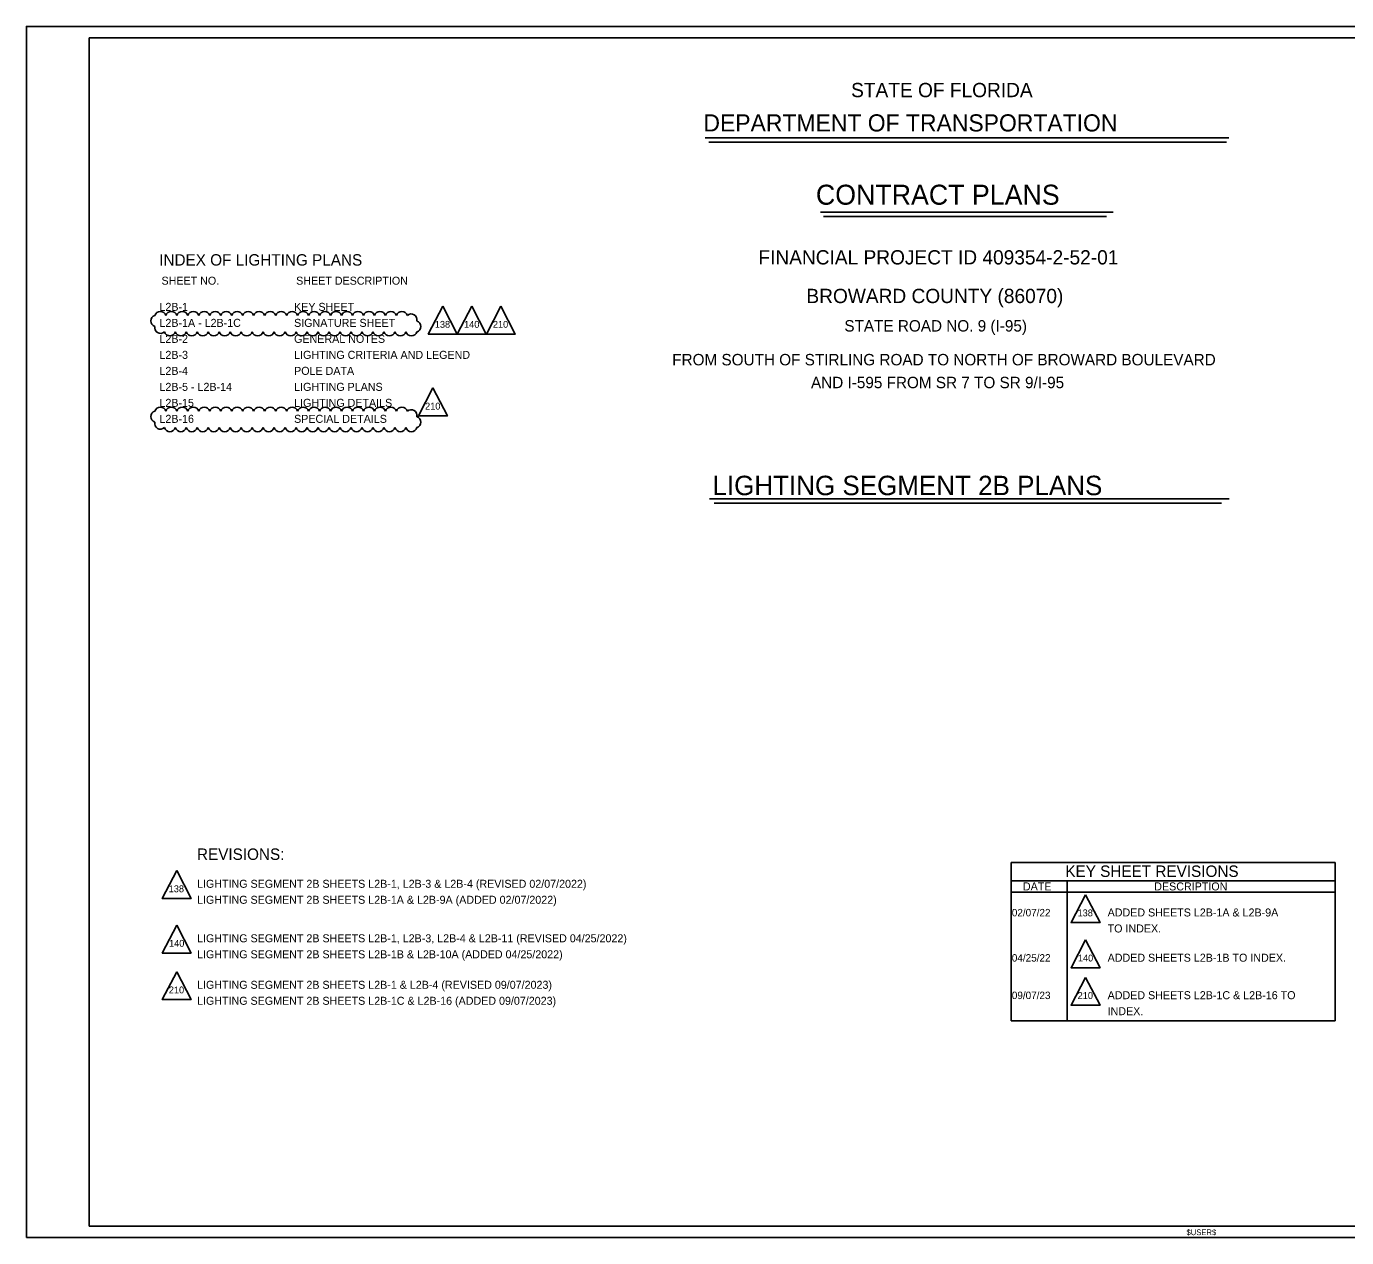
# Model space of a CAD drawing. Extents: x -820.2 to -798.1, y -2199.1 to -2188.5.
# Drawn here: x -820.23 to -808.68, y -2199.12 to -2188.52 of the extents above; entities that cross this region are included whole.
import ezdxf

# ---------------------------------------------------------------- set-up
doc = ezdxf.new("R2010")
doc.units = 0
for name, color, linetype in [('AdhocPoint_dp', 7, 'Continuous'), ('Cloud_dp', 7, 'Continuous'), ('PlotBorder_dp', 7, 'Continuous'), ('SheetBorder_dp', 7, 'Continuous'), ('SumBoxLines_dp', 7, 'Continuous'), ('TextLabel', 7, 'Continuous'), ('TextMinor', 7, 'Continuous'), ('TextNotes', 7, 'Continuous'), ('TextTitle', 7, 'Continuous')]:
    doc.layers.add(name, color=color, linetype=linetype)

msp = doc.modelspace()

# ---------------------------------------------------------------- linework, layer by layer
at = {"layer": 'AdhocPoint_dp'}
msp.add_line((-820.227, -2199.124), (-820.227, -2199.124), dxfattribs=at)
at = {"layer": 'Cloud_dp'}
for points in [[(-816.585, -2190.972), (-816.711, -2191.216), (-816.458, -2191.216)], [(-816.331, -2190.972), (-816.458, -2191.216), (-816.204, -2191.216)], [(-816.077, -2190.972), (-816.203, -2191.216), (-815.95, -2191.216)], [(-816.67, -2191.688), (-816.797, -2191.932), (-816.544, -2191.932)], [(-818.912, -2195.912), (-819.039, -2196.156), (-818.786, -2196.156)], [(-810.961, -2196.123), (-811.088, -2196.367), (-810.834, -2196.367)], [(-818.912, -2196.389), (-819.039, -2196.633), (-818.786, -2196.633)], [(-810.961, -2196.518), (-811.088, -2196.762), (-810.834, -2196.762)], [(-818.912, -2196.797), (-819.039, -2197.041), (-818.786, -2197.041)], [(-810.961, -2196.846), (-811.088, -2197.09), (-810.834, -2197.09)]]:
    msp.add_lwpolyline(points, close=True, dxfattribs=at)
for centre, radius, start, end in [((-819.088, -2191.101), 0.0504, 107.5, 252.5), ((-819.055, -2191.068), 0.0504, 17.5, 162.5), ((-818.959, -2191.068), 0.0504, 17.5, 162.5), ((-818.863, -2191.068), 0.0504, 17.5, 162.5), ((-818.767, -2191.068), 0.0504, 17.5, 162.5), ((-818.671, -2191.068), 0.0504, 17.5, 162.5), ((-818.575, -2191.068), 0.0504, 17.5, 162.5), ((-818.479, -2191.068), 0.0504, 17.5, 162.5), ((-818.383, -2191.068), 0.0504, 17.5, 162.5), ((-818.287, -2191.068), 0.0504, 17.5, 162.5), ((-818.191, -2191.068), 0.0504, 17.5, 162.5), ((-818.094, -2191.068), 0.0504, 17.5, 162.5), ((-817.998, -2191.068), 0.0504, 17.5, 162.5), ((-817.902, -2191.068), 0.0504, 17.5, 162.5), ((-817.806, -2191.068), 0.0504, 17.5, 162.5), ((-817.71, -2191.068), 0.0504, 17.5, 162.5), ((-817.614, -2191.068), 0.0504, 17.5, 162.5), ((-817.518, -2191.068), 0.0504, 17.5, 162.5), ((-817.422, -2191.068), 0.0504, 17.5, 162.5), ((-817.326, -2191.068), 0.0504, 17.5, 162.5), ((-817.23, -2191.068), 0.0504, 17.5, 162.5), ((-817.134, -2191.068), 0.0504, 17.5, 162.5), ((-817.038, -2191.068), 0.0504, 17.5, 162.5), ((-816.942, -2191.068), 0.0504, 17.5, 162.5), ((-816.86, -2191.09), 0.0503, 347.2695, 132.2695), ((-819.054, -2191.16), 0.0503, 167.2695, 312.2695), ((-816.826, -2191.15), 0.0504, 287.5, 72.5), ((-818.972, -2191.182), 0.0504, 197.5, 342.5), ((-818.876, -2191.182), 0.0504, 197.5, 342.5), ((-818.78, -2191.182), 0.0504, 197.5, 342.5), ((-818.684, -2191.182), 0.0504, 197.5, 342.5), ((-818.588, -2191.182), 0.0504, 197.5, 342.5), ((-818.492, -2191.182), 0.0504, 197.5, 342.5), ((-818.396, -2191.182), 0.0504, 197.5, 342.5), ((-818.3, -2191.182), 0.0504, 197.5, 342.5), ((-818.204, -2191.182), 0.0504, 197.5, 342.5), ((-818.108, -2191.182), 0.0504, 197.5, 342.5), ((-818.012, -2191.182), 0.0504, 197.5, 342.5), ((-817.915, -2191.182), 0.0504, 197.5, 342.5), ((-817.819, -2191.182), 0.0504, 197.5, 342.5), ((-817.723, -2191.182), 0.0504, 197.5, 342.5), ((-817.627, -2191.182), 0.0504, 197.5, 342.5), ((-817.531, -2191.182), 0.0504, 197.5, 342.5), ((-817.435, -2191.182), 0.0504, 197.5, 342.5), ((-817.339, -2191.182), 0.0504, 197.5, 342.5), ((-817.243, -2191.182), 0.0504, 197.5, 342.5), ((-817.147, -2191.182), 0.0504, 197.5, 342.5), ((-817.051, -2191.182), 0.0504, 197.5, 342.5), ((-816.955, -2191.182), 0.0504, 197.5, 342.5), ((-816.859, -2191.182), 0.0504, 197.5, 342.5), ((-819.055, -2191.906), 0.0504, 17.5, 162.5), ((-818.959, -2191.906), 0.0504, 17.5, 162.5), ((-818.863, -2191.906), 0.0504, 17.5, 162.5), ((-818.767, -2191.906), 0.0504, 17.5, 162.5), ((-818.671, -2191.906), 0.0504, 17.5, 162.5), ((-818.575, -2191.906), 0.0504, 17.5, 162.5), ((-818.479, -2191.906), 0.0504, 17.5, 162.5), ((-818.383, -2191.906), 0.0504, 17.5, 162.5), ((-818.287, -2191.906), 0.0504, 17.5, 162.5), ((-818.191, -2191.906), 0.0504, 17.5, 162.5), ((-818.094, -2191.906), 0.0504, 17.5, 162.5), ((-817.998, -2191.906), 0.0504, 17.5, 162.5), ((-817.902, -2191.906), 0.0504, 17.5, 162.5), ((-817.806, -2191.906), 0.0504, 17.5, 162.5), ((-817.71, -2191.906), 0.0504, 17.5, 162.5), ((-817.614, -2191.906), 0.0504, 17.5, 162.5), ((-817.518, -2191.906), 0.0504, 17.5, 162.5), ((-817.422, -2191.906), 0.0504, 17.5, 162.5), ((-817.326, -2191.906), 0.0504, 17.5, 162.5), ((-817.23, -2191.906), 0.0504, 17.5, 162.5), ((-817.134, -2191.906), 0.0504, 17.5, 162.5), ((-817.038, -2191.906), 0.0504, 17.5, 162.5), ((-816.942, -2191.906), 0.0504, 17.5, 162.5), ((-816.86, -2191.928), 0.0503, 347.2695, 132.2695), ((-819.088, -2191.938), 0.0504, 107.5, 252.5), ((-819.054, -2191.998), 0.0503, 167.2695, 312.2695), ((-816.826, -2191.987), 0.0504, 287.5, 72.5), ((-818.972, -2192.02), 0.0504, 197.5, 342.5), ((-818.876, -2192.02), 0.0504, 197.5, 342.5), ((-818.78, -2192.02), 0.0504, 197.5, 342.5), ((-818.684, -2192.02), 0.0504, 197.5, 342.5), ((-818.588, -2192.02), 0.0504, 197.5, 342.5), ((-818.492, -2192.02), 0.0504, 197.5, 342.5), ((-818.396, -2192.02), 0.0504, 197.5, 342.5), ((-818.3, -2192.02), 0.0504, 197.5, 342.5), ((-818.204, -2192.02), 0.0504, 197.5, 342.5), ((-818.108, -2192.02), 0.0504, 197.5, 342.5), ((-818.012, -2192.02), 0.0504, 197.5, 342.5), ((-817.915, -2192.02), 0.0504, 197.5, 342.5), ((-817.819, -2192.02), 0.0504, 197.5, 342.5), ((-817.723, -2192.02), 0.0504, 197.5, 342.5), ((-817.627, -2192.02), 0.0504, 197.5, 342.5), ((-817.531, -2192.02), 0.0504, 197.5, 342.5), ((-817.435, -2192.02), 0.0504, 197.5, 342.5), ((-817.339, -2192.02), 0.0504, 197.5, 342.5), ((-817.243, -2192.02), 0.0504, 197.5, 342.5), ((-817.147, -2192.02), 0.0504, 197.5, 342.5), ((-817.051, -2192.02), 0.0504, 197.5, 342.5), ((-816.955, -2192.02), 0.0504, 197.5, 342.5), ((-816.859, -2192.02), 0.0504, 197.5, 342.5)]:
    msp.add_arc(centre, radius, start, end, dxfattribs=at)
at = {"layer": 'PlotBorder_dp'}
msp.add_lwpolyline([(-820.227, -2199.124), (-803.727, -2199.124), (-803.727, -2188.524), (-820.227, -2188.524)], close=True, dxfattribs=at)
at = {"layer": 'SheetBorder_dp'}
for p, q in [((-819.677, -2188.624), (-819.677, -2199.024)), ((-819.677, -2188.624), (-804.277, -2188.624)), ((-819.677, -2199.024), (-804.277, -2199.024))]:
    msp.add_line(p, q, dxfattribs=at)
at = {"layer": 'SumBoxLines_dp'}
for p, q in [((-811.612, -2195.84), (-811.612, -2197.227)), ((-811.612, -2195.84), (-808.777, -2195.84)), ((-808.777, -2195.84), (-808.777, -2197.227)), ((-811.612, -2196), (-808.777, -2196)), ((-811.122, -2196), (-811.122, -2197.227)), ((-811.612, -2196.1), (-808.777, -2196.1)), ((-811.612, -2197.227), (-808.777, -2197.227))]:
    msp.add_line(p, q, dxfattribs=at)
at = {"layer": 'TextTitle'}
for p, q in [((-814.289, -2189.5), (-809.707, -2189.5)), ((-814.257, -2189.538), (-809.729, -2189.538)), ((-813.281, -2190.15), (-810.719, -2190.15)), ((-813.253, -2190.188), (-810.777, -2190.188)), ((-814.252, -2192.659), (-809.704, -2192.659)), ((-814.209, -2192.697), (-809.772, -2192.697))]:
    msp.add_line(p, q, dxfattribs=at)

# ---------------------------------------------------------------- texts
at = {"layer": 'Cloud_dp'}
for s, p in [('138', (-816.654, -2191.161)), ('140', (-816.398, -2191.161)), ('210', (-816.146, -2191.161)), ('210', (-816.739, -2191.877)), ('138', (-818.982, -2196.101)), ('138', (-811.031, -2196.312)), ('140', (-818.979, -2196.578)), ('140', (-811.028, -2196.707)), ('210', (-818.981, -2196.986)), ('210', (-811.03, -2197.035))]:
    msp.add_text(s, height=0.06, rotation=0, dxfattribs=at).set_placement(p)
at = {"layer": 'TextLabel'}
for s, height, p in [('FINANCIAL PROJECT ID 409354-2-52-01', 0.125, (-813.823, -2190.607)), ('INDEX OF LIGHTING PLANS', 0.1, (-819.065, -2190.617)), ('BROWARD COUNTY (86070)', 0.125, (-813.403, -2190.945)), ('L2B-1', 0.07, (-819.063, -2191.013)), ('KEY SHEET', 0.07, (-817.885, -2191.013)), ('L2B-1A - L2B-1C', 0.07, (-819.063, -2191.153)), ('SIGNATURE SHEET', 0.07, (-817.885, -2191.153)), ('STATE ROAD NO. 9 (I-95)', 0.1, (-813.071, -2191.194)), ('L2B-2', 0.07, (-819.063, -2191.293)), ('GENERAL NOTES', 0.07, (-817.885, -2191.293)), ('L2B-3', 0.07, (-819.063, -2191.433)), ('LIGHTING CRITERIA AND LEGEND', 0.07, (-817.885, -2191.433)), ('FROM SOUTH OF STIRLING ROAD TO NORTH OF BROWARD BOULEVARD', 0.1, (-814.577, -2191.49)), ('L2B-4', 0.07, (-819.063, -2191.573)), ('POLE DATA', 0.07, (-817.885, -2191.573)), ('L2B-5 - L2B-14', 0.07, (-819.063, -2191.713)), ('LIGHTING PLANS', 0.07, (-817.885, -2191.713)), ('AND I-595 FROM SR 7 TO SR 9/I-95', 0.1, (-813.363, -2191.69)), ('L2B-15', 0.07, (-819.063, -2191.853)), ('LIGHTING DETAILS', 0.07, (-817.885, -2191.853)), ('L2B-16', 0.07, (-819.063, -2191.993)), ('SPECIAL DETAILS', 0.07, (-817.885, -2191.993)), ('REVISIONS:', 0.1, (-818.735, -2195.818)), ('KEY SHEET REVISIONS', 0.1, (-811.138, -2195.967))]:
    msp.add_text(s, height=height, dxfattribs=at).set_placement(p)
at = {"layer": 'TextMinor'}
for s, height, p in [('02/07/22', 0.065, (-811.606, -2196.312)), ('ADDED SHEETS L2B-1A & L2B-9A ', 0.07, (-810.768, -2196.313)), ('TO INDEX.', 0.07, (-810.768, -2196.453)), ('04/25/22', 0.065, (-811.606, -2196.708)), ('ADDED SHEETS L2B-1B TO INDEX.', 0.07, (-810.768, -2196.709)), ('09/07/23', 0.065, (-811.606, -2197.036)), ('ADDED SHEETS L2B-1C & L2B-16 TO ', 0.07, (-810.768, -2197.037)), ('INDEX.', 0.07, (-810.768, -2197.177)), ('$USER$', 0.05, (-810.078, -2199.102))]:
    msp.add_text(s, height=height, dxfattribs=at).set_placement(p)
at = {"layer": 'TextNotes'}
for s, height, p in [('SHEET NO.', 0.07, (-819.045, -2190.784)), ('SHEET DESCRIPTION', 0.07, (-817.867, -2190.784)), ('LIGHTING SEGMENT 2B SHEETS L2B-1, L2B-3 & L2B-4 (REVISED 02/07/2022)', 0.06998, (-818.734, -2196.062)), ('DATE', 0.07, (-811.509, -2196.085)), ('DESCRIPTION', 0.07, (-810.36, -2196.085)), ('LIGHTING SEGMENT 2B SHEETS L2B-1A & L2B-9A (ADDED 02/07/2022)', 0.06998, (-818.734, -2196.202)), ('LIGHTING SEGMENT 2B SHEETS L2B-1, L2B-3, L2B-4 & L2B-11 (REVISED 04/25/2022)', 0.06998, (-818.734, -2196.539)), ('LIGHTING SEGMENT 2B SHEETS L2B-1B & L2B-10A (ADDED 04/25/2022)', 0.06998, (-818.734, -2196.679)), ('LIGHTING SEGMENT 2B SHEETS L2B-1 & L2B-4 (REVISED 09/07/2023)', 0.06998, (-818.734, -2196.946)), ('LIGHTING SEGMENT 2B SHEETS L2B-1C & L2B-16 (ADDED 09/07/2023)', 0.06998, (-818.734, -2197.086))]:
    msp.add_text(s, height=height, dxfattribs=at).set_placement(p)
at = {"layer": 'TextTitle'}
for s, height, p in [('STATE OF FLORIDA', 0.125, (-813.012, -2189.143)), ('DEPARTMENT OF TRANSPORTATION', 0.15, (-814.304, -2189.443)), ('CONTRACT PLANS', 0.175, (-813.32, -2190.084)), ('LIGHTING SEGMENT 2B PLANS', 0.17, (-814.225, -2192.626))]:
    msp.add_text(s, height=height, dxfattribs=at).set_placement(p)

doc.saveas('drawing.dxf')
